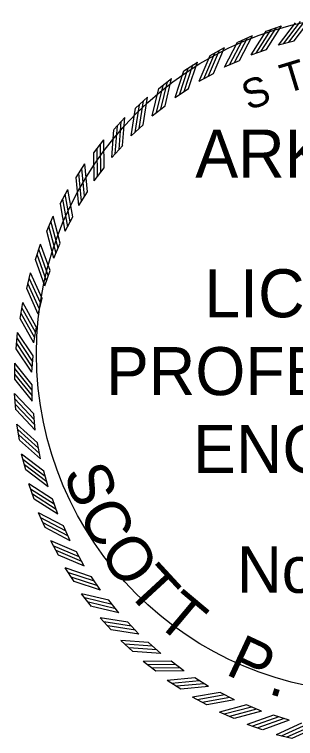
# Model space of a CAD drawing. Extents: x 152 to 3426, y 67 to 2142.
# Drawn here: x 3002.4 to 3095.4, y 310.5 to 550.5 of the extents above; entities that cross this region are included whole.
import ezdxf

# ---------------------------------------------------------------- set-up
doc = ezdxf.new("R2010")
doc.units = 0
doc.layers.add('G-TBLK', color=7, linetype='Continuous')
doc.layers.add('R_Annotation', color=7, linetype='Continuous')

msp = doc.modelspace()

# ---------------------------------------------------------------- linework, layer by layer
at = {"layer": 'G-TBLK'}
msp.add_circle((3122.09, 438.03), 112.43, dxfattribs=at)
at = {"layer": 'R_Annotation'}
for p, q in [((3085.72, 544.9), (3090.78, 546.69)), ((3076.28, 541.27), (3081.17, 543.47)), ((3089.8, 540.35), (3095, 541.72)), ((3067.17, 536.87), (3071.86, 539.47)), ((3080.72, 537.07), (3085.79, 538.86)), ((3071.94, 533.06), (3076.85, 535.26)), ((3058.45, 531.74), (3062.92, 534.71)), ((3063.53, 528.33), (3068.23, 530.93)), ((3050.19, 525.9), (3054.4, 529.24)), ((3055.53, 522.93), (3060, 525.91)), ((3042.44, 519.41), (3046.36, 523.08)), ((3048, 516.88), (3052.22, 520.22)), ((3035.25, 512.29), (3038.85, 516.27)), ((3041.01, 510.23), (3044.93, 513.91)), ((3028.68, 504.61), (3031.93, 508.87)), ((3034.58, 503.03), (3038.19, 507.02)), ((3022.76, 496.4), (3025.65, 500.92)), ((3028.77, 495.32), (3032.03, 499.59)), ((3017.53, 487.74), (3020.05, 492.48)), ((3023.62, 487.16), (3026.52, 491.69)), ((3013.05, 478.68), (3015.16, 483.61)), ((3019.16, 478.6), (3021.67, 483.35)), ((3009.32, 469.27), (3011.02, 474.36)), ((3015.42, 469.7), (3017.53, 474.64)), ((3012.43, 460.52), (3014.12, 465.62)), ((3006.39, 459.59), (3007.66, 464.81)), ((3010.2, 451.13), (3011.47, 456.35)), ((3004.26, 449.71), (3005.09, 455.01)), ((3008.76, 441.58), (3009.6, 446.9)), ((3002.96, 439.67), (3003.35, 445.03)), ((3008.11, 431.95), (3008.51, 437.32)), ((3002.49, 429.57), (3002.44, 434.94)), ((3008.26, 422.3), (3008.22, 427.68)), ((3002.85, 419.46), (3002.36, 424.81)), ((3009.21, 412.7), (3008.72, 418.05)), ((3004.05, 409.42), (3003.12, 414.7)), ((3010.95, 403.2), (3010.01, 408.5)), ((3006.08, 399.51), (3004.71, 404.7)), ((3013.46, 393.88), (3012.1, 399.08)), ((3008.92, 389.8), (3007.13, 394.86)), ((3016.74, 384.8), (3014.95, 389.87)), ((3012.54, 380.36), (3010.34, 385.25)), ((3020.76, 376.02), (3018.55, 380.93)), ((3016.94, 371.25), (3014.34, 375.95)), ((3025.48, 367.61), (3022.88, 372.31)), ((3022.07, 362.54), (3019.1, 367)), ((3030.89, 359.61), (3027.9, 364.08)), ((3027.91, 354.27), (3024.57, 358.48)), ((3036.93, 352.09), (3033.59, 356.3)), ((3034.41, 346.52), (3030.74, 350.44)), ((3043.58, 345.09), (3039.9, 349.01)), ((3041.52, 339.33), (3037.54, 342.93)), ((3050.78, 338.66), (3046.79, 342.27)), ((3049.21, 332.76), (3044.94, 336.01)), ((3058.49, 332.85), (3054.22, 336.12)), ((3057.41, 326.84), (3052.89, 329.73)), ((3066.65, 327.7), (3062.12, 330.6)), ((3066.07, 321.62), (3061.33, 324.13)), ((3075.21, 323.24), (3070.46, 325.75)), ((3084.11, 319.5), (3079.17, 321.61)), ((3075.14, 317.13), (3070.2, 319.24)), ((3093.29, 316.51), (3088.19, 318.21)), ((3084.54, 313.4), (3079.45, 315.1)), ((3094.22, 310.47), (3089, 311.74))]:
    msp.add_line(p, q, dxfattribs=at)
for points in [[(3089.8, 540.34), (3095.42, 547.73)], [(3091.47, 540.77), (3097.1, 548.15)], [(3093.26, 541.28), (3098.89, 548.66)], [(3094.99, 541.72), (3100.62, 549.1)], [(3080.72, 537.07), (3085.71, 544.89)], [(3082.35, 537.63), (3087.35, 545.45)], [(3084.09, 538.29), (3089.09, 546.11)], [(3085.78, 538.87), (3090.78, 546.69)], [(3075.2, 534.55), (3079.54, 542.76)], [(3076.84, 535.26), (3081.18, 543.47)], [(3071.94, 533.05), (3076.27, 541.26)], [(3073.52, 533.74), (3077.86, 541.95)], [(3065.04, 529.15), (3068.68, 537.69)], [(3066.65, 530.08), (3070.3, 538.62)], [(3068.22, 530.93), (3071.87, 539.47)], [(3063.52, 528.32), (3067.17, 536.86)], [(3058.5, 524.93), (3061.42, 533.74)], [(3060, 525.91), (3062.92, 534.72)], [(3055.53, 522.92), (3058.45, 531.73)], [(3056.97, 523.86), (3059.9, 532.67)], [(3050.8, 519.12), (3052.99, 528.15)], [(3052.21, 520.22), (3054.4, 529.24)], [(3048, 516.87), (3050.19, 525.89)], [(3049.37, 517.93), (3051.55, 526.96)], [(3043.61, 512.7), (3045.04, 521.87)], [(3044.92, 513.91), (3046.36, 523.08)], [(3041, 510.22), (3042.44, 519.4)], [(3042.27, 511.39), (3043.71, 520.57)], [(3038.18, 507.02), (3038.85, 516.28)], [(3036.97, 505.7), (3037.64, 514.96)], [(3034.58, 503.02), (3035.25, 512.28)], [(3035.75, 504.29), (3036.42, 513.55)], [(3032.03, 499.59), (3031.93, 508.88)], [(3030.93, 498.18), (3030.83, 507.47)], [(3028.77, 495.31), (3028.68, 504.6)], [(3029.83, 496.68), (3029.74, 505.96)], [(3025.53, 490.19), (3024.67, 499.43)], [(3026.51, 491.68), (3025.65, 500.93)], [(3024.56, 488.6), (3023.7, 497.84)], [(3023.62, 487.15), (3022.76, 496.39)], [(3021.67, 483.35), (3020.04, 492.49)], [(3020.81, 481.78), (3019.19, 490.92)], [(3019.16, 478.59), (3017.54, 487.73)], [(3019.98, 480.11), (3018.36, 489.25)], [(3017.53, 474.64), (3015.15, 483.62)], [(3016.11, 471.27), (3013.74, 480.25)], [(3016.81, 473), (3014.44, 481.98)], [(3015.42, 469.69), (3013.05, 478.67)], [(3014.12, 465.62), (3011.01, 474.37)], [(3012.99, 462.15), (3009.88, 470.9)], [(3013.54, 463.93), (3010.43, 472.68)], [(3012.43, 460.51), (3009.32, 469.26)], [(3011.47, 456.35), (3007.65, 464.81)], [(3010.63, 452.8), (3006.81, 461.26)], [(3011.03, 454.62), (3007.21, 463.08)], [(3010.21, 451.12), (3006.39, 459.59)], [(3009.59, 446.89), (3005.09, 455.01)], [(3009.05, 443.28), (3004.55, 451.4)], [(3009.3, 445.13), (3004.8, 453.25)], [(3008.77, 441.58), (3004.26, 449.7)], [(3008.5, 437.31), (3003.35, 445.03)], [(3008.36, 435.53), (3003.2, 443.25)], [(3008.12, 431.95), (3002.96, 439.67)], [(3008.26, 433.67), (3003.1, 441.39)], [(3008.21, 427.67), (3002.43, 434.94)], [(3008.21, 425.89), (3002.43, 433.15)], [(3008.27, 424.02), (3002.49, 431.29)], [(3008.27, 422.3), (3002.49, 429.56)], [(3008.72, 418.04), (3002.36, 424.81)], [(3008.86, 416.26), (3002.51, 423.03)], [(3009.07, 414.41), (3002.72, 421.18)], [(3009.22, 412.69), (3002.86, 419.46)], [(3010.01, 408.49), (3003.12, 414.71)], [(3010.31, 406.73), (3003.41, 412.95)], [(3010.67, 404.9), (3003.78, 411.12)], [(3010.96, 403.19), (3004.06, 409.41)], [(3012.09, 399.08), (3004.71, 404.7)], [(3012.53, 397.34), (3005.15, 402.97)], [(3013.05, 395.55), (3005.66, 401.18)], [(3013.47, 393.88), (3006.09, 399.5)], [(3014.95, 389.86), (3007.12, 394.86)], [(3015.53, 388.17), (3007.7, 393.17)], [(3016.19, 386.43), (3008.36, 391.43)], [(3016.75, 384.8), (3008.92, 389.8)], [(3018.55, 380.92), (3010.34, 385.26)], [(3019.27, 379.28), (3011.06, 383.62)], [(3020.07, 377.6), (3011.86, 381.94)], [(3020.76, 376.02), (3012.55, 380.36)], [(3022.88, 372.31), (3014.34, 375.95)], [(3023.73, 370.73), (3015.19, 374.38)], [(3024.67, 369.12), (3016.13, 372.77)], [(3025.49, 367.6), (3016.95, 371.25)], [(3027.9, 364.08), (3019.09, 367)], [(3028.88, 362.58), (3020.07, 365.51)], [(3029.95, 361.05), (3021.14, 363.98)], [(3030.89, 359.61), (3022.08, 362.53)], [(3033.59, 356.29), (3024.57, 358.48)], [(3034.69, 354.88), (3025.67, 357.07)], [(3035.88, 353.45), (3026.86, 355.63)], [(3036.94, 352.08), (3027.92, 354.27)], [(3039.9, 349), (3030.73, 350.44)], [(3041.11, 347.69), (3031.94, 349.12)], [(3042.42, 346.36), (3033.25, 347.79)], [(3043.59, 345.09), (3034.42, 346.52)], [(3046.79, 342.26), (3037.53, 342.93)], [(3048.11, 341.05), (3038.85, 341.72)], [(3049.52, 339.83), (3040.26, 340.5)], [(3050.79, 338.66), (3041.53, 339.33)], [(3054.22, 336.11), (3044.94, 336.01)], [(3055.63, 335.01), (3046.35, 334.92)], [(3057.14, 333.91), (3047.85, 333.82)], [(3058.5, 332.85), (3049.22, 332.76)], [(3062.13, 330.59), (3052.88, 329.73)], [(3063.62, 329.61), (3054.38, 328.75)], [(3065.22, 328.64), (3055.97, 327.78)], [(3066.66, 327.7), (3057.42, 326.84)], [(3070.46, 325.75), (3061.32, 324.13)], [(3072.04, 324.9), (3062.89, 323.27)], [(3073.7, 324.06), (3064.56, 322.44)], [(3075.22, 323.24), (3066.08, 321.62)], [(3079.17, 321.61), (3070.2, 319.24)], [(3080.81, 320.89), (3071.83, 318.52)], [(3082.54, 320.19), (3073.56, 317.82)], [(3084.12, 319.5), (3075.14, 317.13)], [(3088.19, 318.2), (3079.44, 315.1)], [(3089.88, 317.62), (3081.13, 314.52)], [(3091.66, 317.07), (3082.91, 313.97)], [(3093.3, 316.51), (3084.55, 313.4)], [(3097.46, 315.55), (3089, 311.73)], [(3099.2, 315.11), (3090.73, 311.3)], [(3101.02, 314.71), (3092.55, 310.89)], [(3102.69, 314.29), (3094.23, 310.47)]]:
    msp.add_lwpolyline(points, dxfattribs=at)

# ---------------------------------------------------------------- texts
for s, height, rotation, p in [('T', 9.76, 16.9015, (3092.19, 524.16)), ('S', 9.76, 19.7726, (3079.78, 518.59)), ('S', 14.83, 289.7007, (3018.44, 398.66)), ('C', 14.83, 296.9967, (3023.21, 385.35)), ('O', 14.83, 304.6575, (3029.99, 372.15)), ('T', 14.83, 312.6831, (3038.91, 359.41)), ('T', 14.83, 319.9791, (3048.5, 349.02)), ('P', 14.83, 334.9359, (3071.84, 331.94)), ('.', 14.83, 342.9615, (3085.97, 325.45))]:
    msp.add_text(s, height=height, rotation=rotation, dxfattribs=at).set_placement(p)
for s, height, p in [('ARKANSAS', 15.932, (3062.24, 496.39)), ('LICENSED', 15.932, (3065.27, 450.08)), ('PROFESSIONAL', 15.9321, (3032.65, 424.28)), ('ENGINEER', 15.932, (3061.48, 398.49)), ('No.10887', 15.363, (3076.04, 358.76))]:
    msp.add_text(s, height=height, dxfattribs=at).set_placement(p)

doc.saveas('drawing.dxf')
